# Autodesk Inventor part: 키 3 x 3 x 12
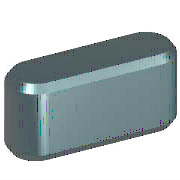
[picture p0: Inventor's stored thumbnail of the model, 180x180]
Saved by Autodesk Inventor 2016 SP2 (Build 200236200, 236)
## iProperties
Created: 2012-02
Part Number: 키 3 x 3 x 12
Material: 강철, 연강
Description: 키 및 해당 키홈
Document SubType Name: Modeling
Standard: KS B 1311
Designer: mduedu
Standards Organization: KS
Language: ko-KR
Size Designation: 3 x 3 x 12
Categories: <MemberInstance><Categories><Category DisplayName="샤프트 부품" InternalName="7f7aeb1f-a693-4053-b835-cee3144e0d98" Mnemonic="SHFT"><Category DisplayName="키" Interna
Density: 1 g/cm^3
Appearance: 노란색
IsCustomPart: 1
Author: mduedu
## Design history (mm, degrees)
workplane "Work Plane1"
workplane "Work Plane2"
sketch "스케치1"
  geometry: L1 (1.5, 1.5)-(10.5, 1.5); L2 (10.5, -1.5)-(1.5, -1.5); L3 (0, 9.4)-(0, -7.4) reference; L4 (-5, 0)-(30, 0) reference; L5 (12, 0)-(12, 7); A1 r 1.5 centre (1.5, 0) between (1.5, 1.5) and (1.5, -1.5); A2 r 1.5 centre (10.5, 0) between (10.5, -1.5) and (10.5, 1.5)
  constraints: 6 end point, 5 point on circle, 4 tangent, 3 point on line, 2 centre point, 1 horizontal, 1 parallel, 1 perpendicular
  dimensions: "d0" = 1.5 radius of A1 (= 0.5 x PB); "d13" = 1.5 radius of A2 (= 0.5 x PB); "d14" = 12 distance between parallel lines of L5 L3 (= NLG)
extrude "본체1" new body sketch "스케치1" taper "d3" = 0 deg; stored distance "d4" = 10
workplane "Work Plane3"
body "Solid1"
chamfer "모따기1" distance "d8" = 0.25 (= PHH); stored, may be unused: second distance "d9" = 0.25 (= PHH), angle "d15" = 45 deg
other parameters: "d1" = -1.8 (= -PNT), "d2" = 1.2 (= PH - PNT), "NLG" = 12 [user parameter; used in 3 equation terms], "PB" = 3 [user parameter; used in 2 equation terms], "PNT" = 1.8 [user parameter; used in 2 equation terms], "PH" = 3 [user parameter; used in 1 equation term], "PHH" = 0.25 [user parameter; used in 2 equation terms], "d10" = 0, "d16" = 0, "d17" = 0, "d18" = 0, "WDMIN" = 8 [user parameter], "PLB2" = 12 (= NLG) [user parameter], "PLB1" = 12 (= NLG) [user parameter], "RR" = 0.08 [user parameter], "PUEB" = 1.4 [user parameter]
